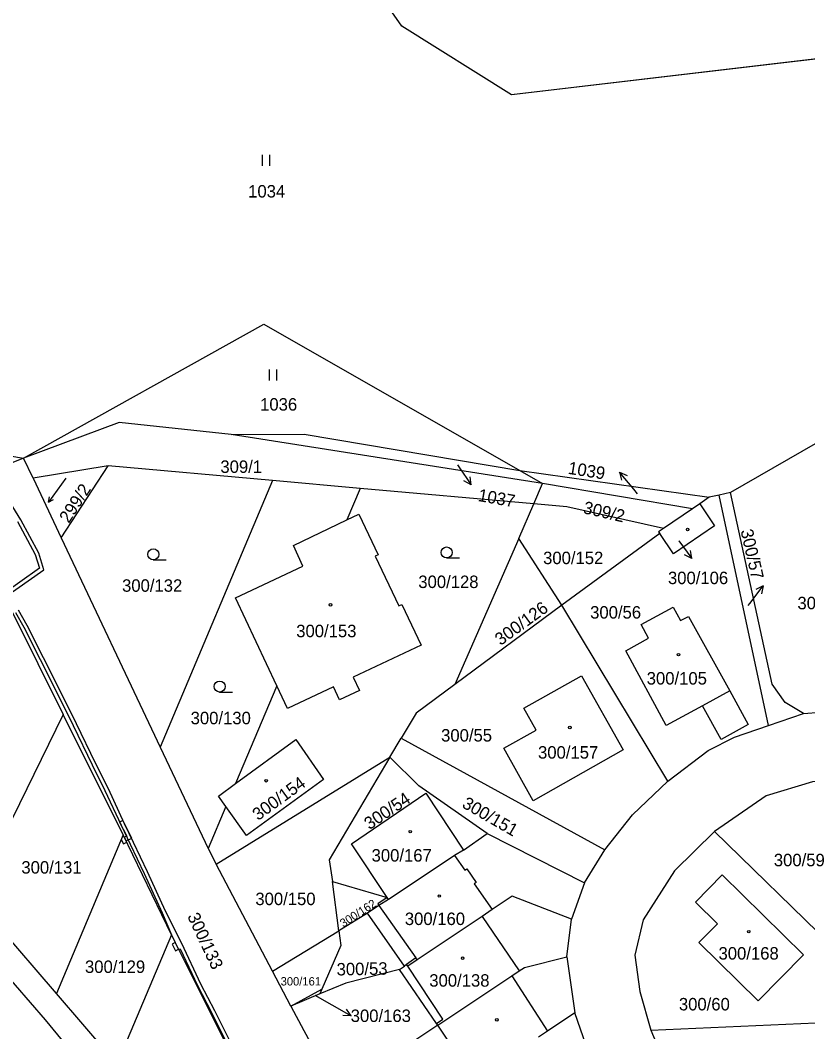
# Model space of a CAD drawing. Extents: x -757266 to -753360, y -1162585 to -1157740.
# Drawn here: x -754815.2 to -754707.7, y -1160582.8 to -1160444.8 of the extents above; entities that cross this region are included whole.
import ezdxf

# ---------------------------------------------------------------- set-up
doc = ezdxf.new("R2010")
doc.units = 0
for name, color, linetype in [('Hranice kat_území', 7, 'Continuous'), ('Hranice parcel', 7, 'Continuous'), ('Parcelní čísla', 7, 'Continuous'), ('Pop  PČ popisy', 7, 'Continuous'), ('Vnitřní kresba', 7, 'Continuous'), ('Věcná břemena k části', 7, 'Continuous'), ('Značky budov', 7, 'Continuous'), ('Značky kultur', 7, 'Continuous')]:
    doc.layers.add(name, color=color, linetype=linetype)

msp = doc.modelspace()

# ---------------------------------------------------------------- linework, layer by layer
at = {"layer": 'Hranice kat_území'}
msp.add_lwpolyline([(-754561.41, -1160428.29), (-754599.4, -1160427.7), (-754608.96, -1160459.95), (-754612, -1160470.2), (-754628.81, -1160464.16), (-754656.06, -1160454.38), (-754658.34, -1160453.56), (-754670.71, -1160445.87), (-754748.18, -1160454.98), (-754763.13, -1160445.62), (-754770.6, -1160434.89), (-754825.24, -1160422.53), (-754831.13, -1160423.76), (-754836.68, -1160424.92)], dxfattribs=at)
at = {"layer": 'Hranice parcel'}
for p, q in [((-754670.71, -1160445.87), (-754748.18, -1160454.98)), ((-754699.35, -1160498.35), (-754718.28, -1160509.25)), ((-754743.91, -1160508.02), (-754786.41, -1160501.34)), ((-754813.46, -1160507.31), (-754814.75, -1160504.58)), ((-754803.2, -1160505.6), (-754813.46, -1160507.31)), ((-754809.62, -1160515.44), (-754803.2, -1160505.6)), ((-754780.79, -1160507.61), (-754803.2, -1160505.6)), ((-754813.46, -1160507.31), (-754809.62, -1160515.44)), ((-754747.02, -1160506.24), (-754721.17, -1160509.88)), ((-754747.02, -1160506.24), (-754743.91, -1160508.02)), ((-754780.79, -1160507.61), (-754796.12, -1160544.01)), ((-754768.82, -1160508.68), (-754780.79, -1160507.61)), ((-754768.82, -1160508.68), (-754770.64, -1160512.99)), ((-754745.12, -1160510.8), (-754768.82, -1160508.68)), ((-754745.12, -1160510.8), (-754743.91, -1160508.02)), ((-754723.47, -1160511.47), (-754743.91, -1160508.02)), ((-754721.17, -1160509.88), (-754722.48, -1160510.8)), ((-754719.84, -1160509.59), (-754721.17, -1160509.88)), ((-754718.28, -1160509.25), (-754719.84, -1160509.59)), ((-754713.08, -1160541.04), (-754719.84, -1160509.59)), ((-754747.17, -1160515.5), (-754745.12, -1160510.8)), ((-754723.47, -1160511.47), (-754727.43, -1160514.15)), ((-754722.48, -1160510.8), (-754723.47, -1160511.47)), ((-754809.62, -1160515.44), (-754796.12, -1160544.01)), ((-754747.17, -1160515.5), (-754755.88, -1160535.43)), ((-754741.28, -1160524.64), (-754747.17, -1160515.5)), ((-754727.94, -1160514.85), (-754741.28, -1160524.64)), ((-754741.28, -1160524.64), (-754755.88, -1160535.43)), ((-754726.81, -1160548.63), (-754741.28, -1160524.64)), ((-754816.26, -1160525.62), (-754809.33, -1160539.55)), ((-754780.19, -1160535.61), (-754785.83, -1160548.97)), ((-754809.33, -1160539.55), (-754821.59, -1160564.48)), ((-754801.15, -1160555.98), (-754809.33, -1160539.55)), ((-754713.08, -1160541.04), (-754708.3, -1160539.4)), ((-754764.77, -1160545.37), (-754763.24, -1160542.79)), ((-754763.24, -1160542.79), (-754735.43, -1160558)), ((-754796.12, -1160544.01), (-754789.58, -1160557.84)), ((-754788.47, -1160559.96), (-754764.77, -1160545.37)), ((-754787.15, -1160552.09), (-754789.58, -1160557.84)), ((-754754.7, -1160558.03), (-754751.49, -1160555.79)), ((-754751.49, -1160555.79), (-754738.19, -1160562.51)), ((-754720.47, -1160555.5), (-754694.29, -1160581.04)), ((-754801.15, -1160555.98), (-754810.26, -1160577.6)), ((-754794.56, -1160569.62), (-754801.15, -1160555.98)), ((-754789.58, -1160557.84), (-754788.47, -1160559.96)), ((-754738.19, -1160562.51), (-754735.43, -1160558)), ((-754780.78, -1160574.56), (-754788.47, -1160559.96)), ((-754771.72, -1160569.05), (-754772.61, -1160562.35)), ((-754772.61, -1160562.35), (-754765.14, -1160564.5)), ((-754738.19, -1160562.51), (-754739.97, -1160567.47)), ((-754810.26, -1160577.6), (-754821.59, -1160564.48)), ((-754764.95, -1160564.79), (-754765.14, -1160564.5)), ((-754767.81, -1160566.67), (-754771.72, -1160569.05)), ((-754762.78, -1160573.86), (-754767.81, -1160566.67)), ((-754740.63, -1160572.62), (-754739.97, -1160567.47)), ((-754794.56, -1160569.62), (-754801.98, -1160587.2)), ((-754781.89, -1160594.97), (-754794.56, -1160569.62)), ((-754780.78, -1160574.56), (-754771.72, -1160569.05)), ((-754740.63, -1160572.62), (-754739.52, -1160580.26)), ((-754778.27, -1160579.33), (-754780.78, -1160574.56)), ((-754763.44, -1160574.32), (-754762.78, -1160573.86)), ((-754801.98, -1160587.2), (-754810.26, -1160577.6)), ((-754778.27, -1160579.33), (-754774.04, -1160577.01)), ((-754774.33, -1160577.68), (-754778.27, -1160579.33)), ((-754774.04, -1160577.01), (-754774.33, -1160577.68)), ((-754729.14, -1160582.6), (-754694.29, -1160581.04))]:
    msp.add_line(p, q, dxfattribs=at)
for points in [[(-754748.18, -1160454.98), (-754763.13, -1160445.62), (-754770.6, -1160434.89)], [(-754814.75, -1160504.58), (-754781.96, -1160486.26), (-754747.02, -1160506.24)], [(-754786.41, -1160501.34), (-754801.72, -1160499.7), (-754814.75, -1160504.58)], [(-754786.41, -1160501.34), (-754776.46, -1160501.29), (-754747.02, -1160506.24)], [(-754900.14, -1160504.92), (-754886.65, -1160509.79), (-754875.4, -1160511.64), (-754856.28, -1160511.06), (-754826.49, -1160502.54), (-754814.75, -1160504.58)], [(-754814.75, -1160504.58), (-754827.27, -1160509.62), (-754832.15, -1160509.43)], [(-754708.3, -1160539.4), (-754710.83, -1160537.88), (-754712.6, -1160535.4), (-754718.28, -1160509.25)], [(-754727.43, -1160514.15), (-754740.6, -1160511.2), (-754745.12, -1160510.8)], [(-754722.48, -1160510.8), (-754720.44, -1160513.8), (-754726.07, -1160517.61), (-754727.94, -1160514.85)], [(-754780.19, -1160535.61), (-754785.81, -1160523.61), (-754776.63, -1160519.29), (-754777.92, -1160516.46), (-754770.64, -1160512.99)], [(-754770.64, -1160512.99), (-754769, -1160512.21), (-754766.36, -1160517.76), (-754766.76, -1160517.95), (-754763.54, -1160524.72), (-754763.14, -1160524.53), (-754760.49, -1160530.08), (-754769.76, -1160534.46), (-754768.91, -1160536.27), (-754771.62, -1160537.55), (-754772.47, -1160535.75), (-754778.72, -1160538.71), (-754780.19, -1160535.61)], [(-754727.43, -1160514.15), (-754728.1, -1160514.61), (-754727.94, -1160514.85)], [(-754725.09, -1160526.73), (-754724, -1160526.15), (-754718.35, -1160536.32), (-754722.08, -1160538.36), (-754727.04, -1160541.04), (-754732.57, -1160530.83), (-754729.46, -1160529.12), (-754730.48, -1160527.27), (-754726.1, -1160524.9), (-754725.09, -1160526.73)], [(-754744.78, -1160541.67), (-754746.49, -1160538.67), (-754738.63, -1160534.24), (-754732.93, -1160544.34), (-754745.21, -1160551.32), (-754749.2, -1160544.12), (-754744.78, -1160541.67)], [(-754755.88, -1160535.43), (-754761.19, -1160539.36), (-754763.24, -1160542.79)], [(-754708.3, -1160539.4), (-754703.69, -1160539.02), (-754695.7, -1160539.88)], [(-754726.81, -1160548.63), (-754721.31, -1160544.46), (-754717.73, -1160542.64), (-754713.08, -1160541.04)], [(-754785.83, -1160548.97), (-754777.59, -1160542.96), (-754773.84, -1160548.39), (-754784.34, -1160556.04), (-754787.15, -1160552.09)], [(-754764.77, -1160545.37), (-754773.06, -1160559.36), (-754772.61, -1160562.35)], [(-754751.49, -1160555.79), (-754760.81, -1160549.27), (-754764.77, -1160545.37)], [(-754787.15, -1160552.09), (-754788.15, -1160550.69), (-754785.83, -1160548.97)], [(-754735.43, -1160558), (-754731.66, -1160553.22), (-754726.81, -1160548.63)], [(-754682.09, -1160554.71), (-754692.82, -1160549.97), (-754700.68, -1160548.61), (-754707.08, -1160548.74), (-754713.39, -1160550.62), (-754720.47, -1160555.5)], [(-754765.14, -1160564.5), (-754770.01, -1160557.17), (-754759.86, -1160550.29), (-754754.7, -1160558.03)], [(-754720.47, -1160555.5), (-754725.91, -1160560.87), (-754730.19, -1160567.56), (-754731.32, -1160572.38), (-754730.67, -1160577.36), (-754729.14, -1160582.6)], [(-754832.33, -1160557.56), (-754811.8, -1160581.2), (-754788.57, -1160609.52), (-754757.81, -1160649.38), (-754749.73, -1160667.84), (-754718.09, -1160730.78), (-754707.28, -1160759.93), (-754701.46, -1160778.37), (-754686.64, -1160826.48), (-754676.87, -1160861.18), (-754663.2, -1160911.68), (-754637.02, -1161012.69), (-754632.76, -1161025.61)], [(-754754.7, -1160558.03), (-754755.94, -1160558.77), (-754764.7, -1160564.63), (-754764.95, -1160564.79)], [(-754720.06, -1160568.1), (-754723.04, -1160565.14), (-754719.39, -1160561.44), (-754708.33, -1160572.35), (-754714.51, -1160578.61), (-754722.58, -1160570.66), (-754720.06, -1160568.1)], [(-754764.95, -1160564.79), (-754766.26, -1160565.6), (-754767.81, -1160566.67)], [(-754739.97, -1160567.47), (-754748.08, -1160564.34), (-754750.82, -1160566.17), (-754752.18, -1160567.09), (-754761.03, -1160573.02), (-754762.33, -1160573.9), (-754762.49, -1160573.66), (-754762.78, -1160573.86)], [(-754771.72, -1160569.05), (-754771.45, -1160571.08), (-754774.04, -1160577.01)], [(-754758.21, -1160581.94), (-754748.1, -1160575.19), (-754747.12, -1160574.53), (-754746.4, -1160574.05), (-754740.63, -1160572.62)], [(-754763.44, -1160574.32), (-754770.77, -1160576.18), (-754774.33, -1160577.68)], [(-754758.21, -1160581.94), (-754758.38, -1160581.7), (-754763.44, -1160574.32)], [(-754778.27, -1160579.33), (-754776.51, -1160582.67), (-754772.11, -1160590.8)], [(-754739.52, -1160580.26), (-754743.24, -1160582.74), (-754744.49, -1160583.58)], [(-754734.33, -1160594.03), (-754736.45, -1160589.03), (-754739.52, -1160580.26)], [(-754758.21, -1160581.94), (-754768.98, -1160589.13), (-754772.11, -1160590.8)], [(-754754.41, -1160590.2), (-754754.53, -1160590.01), (-754753.35, -1160589.23), (-754758.21, -1160581.94)], [(-754729.14, -1160582.6), (-754725.55, -1160591.14), (-754723.55, -1160595.26), (-754719.68, -1160601.5), (-754710.21, -1160615.49)]]:
    msp.add_lwpolyline(points, dxfattribs=at)
at = {"layer": 'Pop  PČ popisy'}
for p, q in [((-754755.54, -1160505.46), (-754755.35, -1160505.73)), ((-754755.35, -1160505.73), (-754753.672, -1160508.218)), ((-754753.672, -1160508.218), (-754753.817, -1160507.108)), ((-754731.49, -1160508.77), (-754733.419, -1160506.471)), ((-754733.419, -1160506.471), (-754732.392, -1160506.916)), ((-754733.419, -1160506.471), (-754733.159, -1160507.56)), ((-754753.672, -1160508.218), (-754754.647, -1160507.668)), ((-754730.95, -1160509.42), (-754731.49, -1160508.77)), ((-754725.32, -1160515.82), (-754725.31, -1160515.84)), ((-754725.31, -1160515.84), (-754723.546, -1160518.268)), ((-754723.546, -1160518.268), (-754723.73, -1160517.163)), ((-754723.546, -1160518.268), (-754724.54, -1160517.752)), ((-754715.64, -1160524.38), (-754713.834, -1160521.983)), ((-754713.834, -1160521.983), (-754714.837, -1160522.482)), ((-754713.834, -1160521.983), (-754714.037, -1160523.084)), ((-754715.86, -1160524.68), (-754715.64, -1160524.38)), ((-754775.01, -1160577.82), (-754772.66, -1160579.17)), ((-754772.66, -1160579.17), (-754770.061, -1160580.67)), ((-754770.061, -1160580.67), (-754771.179, -1160580.603)), ((-754770.061, -1160580.67), (-754770.678, -1160579.736))]:
    msp.add_line(p, q, dxfattribs=at)
at = {"layer": 'Vnitřní kresba'}
for p, q in [((-754718.35, -1160536.32), (-754715.87, -1160540.92)), ((-754719.54, -1160542.94), (-754722.08, -1160538.36)), ((-754715.87, -1160540.92), (-754719.54, -1160542.94)), ((-754755.94, -1160558.77), (-754754.53, -1160560.8)), ((-754754.53, -1160560.8), (-754754.26, -1160560.61)), ((-754754.26, -1160560.61), (-754752.98, -1160562.46)), ((-754752.98, -1160562.46), (-754753.25, -1160562.65)), ((-754753.25, -1160562.65), (-754750.82, -1160566.17)), ((-754765.14, -1160564.5), (-754766.41, -1160565.38)), ((-754766.41, -1160565.38), (-754766.26, -1160565.6)), ((-754766.26, -1160565.6), (-754761.21, -1160572.75)), ((-754752.18, -1160567.09), (-754747.12, -1160574.53)), ((-754761.21, -1160572.75), (-754762.49, -1160573.66)), ((-754761.03, -1160573.02), (-754761.21, -1160572.75)), ((-754757.53, -1160581.12), (-754762.33, -1160573.9)), ((-754748.1, -1160575.19), (-754743.24, -1160582.74)), ((-754758.38, -1160581.7), (-754757.53, -1160581.12))]:
    msp.add_line(p, q, dxfattribs=at)
at = {"layer": 'Věcná břemena k části'}
for points in [[(-754817.48, -1160523.68), (-754812, -1160519.79), (-754812.69, -1160517.51), (-754815.13, -1160512.96), (-754816.56, -1160510.59)], [(-754815.57, -1160513.2), (-754813.15, -1160517.71), (-754812.58, -1160519.59), (-754817.96, -1160523.41)], [(-754785.53, -1160586.25), (-754788.65, -1160580), (-754790.56, -1160576.32), (-754793.17, -1160570.81), (-754795.39, -1160566.38), (-754797.83, -1160561.02), (-754799.74, -1160557.01), (-754800.97, -1160554.44), (-754803.18, -1160549.67), (-754804.94, -1160546.17), (-754807.52, -1160540.81), (-754809.89, -1160536.05), (-754812.05, -1160531.82), (-754814.27, -1160527.38), (-754815.45, -1160525.31)], [(-754815.85, -1160525.61), (-754814.71, -1160527.62), (-754812.49, -1160532.04), (-754810.33, -1160536.27), (-754807.96, -1160541.03), (-754805.38, -1160546.39), (-754803.64, -1160549.89), (-754801.43, -1160554.66), (-754800.2, -1160557.23), (-754798.29, -1160561.24), (-754795.85, -1160566.6), (-754794.56, -1160569.62), (-754794.04, -1160570.67), (-754793.59, -1160571.56), (-754793.39, -1160571.53), (-754791, -1160576.54), (-754789.09, -1160580.22), (-754785.97, -1160586.47)]]:
    msp.add_lwpolyline(points, dxfattribs=at)
for points in [[(-754801, -1160556.3), (-754800.77, -1160556.76), (-754799.96, -1160556.42), (-754801.2, -1160554.01), (-754801.65, -1160554.24), (-754800.66, -1160556.16)], [(-754801.41, -1160556.6), (-754801.12, -1160557.2), (-754800.67, -1160556.98), (-754800.77, -1160556.76), (-754801, -1160556.3), (-754801.1, -1160556.08), (-754801.21, -1160556.13)], [(-754794.04, -1160570.67), (-754794.48, -1160570.89), (-754794.03, -1160571.79), (-754793.59, -1160571.56)]]:
    msp.add_lwpolyline(points, close=True, dxfattribs=at)
at = {"layer": 'Značky budov'}
for centre in [(-754724.1268, -1160514.2892), (-754772.8668, -1160524.5792), (-754725.3668, -1160531.3792), (-754740.1968, -1160541.3092), (-754781.6468, -1160548.5792), (-754761.9768, -1160555.5292), (-754758.0168, -1160564.3092), (-754715.7868, -1160569.1792), (-754754.8268, -1160572.7892), (-754750.1668, -1160581.1992)]:
    msp.add_circle(centre, 0.175, dxfattribs=at)
at = {"layer": 'Značky kultur'}
for p, q in [((-754782.161, -1160464.67), (-754782.161, -1160463.17)), ((-754781.16, -1160464.67), (-754781.16, -1160463.17)), ((-754781.181, -1160493.96), (-754781.181, -1160492.46)), ((-754780.18, -1160493.96), (-754780.18, -1160492.46)), ((-754808.97, -1160507.3), (-754811.333, -1160510.552)), ((-754811.333, -1160510.552), (-754811.22, -1160509.825)), ((-754811.333, -1160510.552), (-754810.676, -1160510.22)), ((-754797.043, -1160518.44), (-754795.293, -1160518.44)), ((-754757.013, -1160518.18), (-754755.263, -1160518.18)), ((-754787.993, -1160536.47), (-754786.243, -1160536.47))]:
    msp.add_line(p, q, dxfattribs=at)
for centre in [(-754797.0429, -1160517.6898), (-754757.0129, -1160517.4298), (-754787.9929, -1160535.7198)]:
    msp.add_circle(centre, 0.75, dxfattribs=at)

# ---------------------------------------------------------------- texts
at = {"layer": 'Parcelní čísla'}
for s, height, p in [('1034', 1.7, (-754784.1, -1160468.99)), ('1036', 1.7, (-754782.47, -1160498.07)), ('309/1', 1.7, (-754787.89, -1160506.57)), ('300/152', 1.7, (-754743.85, -1160519.02)), ('300/106', 1.7, (-754726.81, -1160521.748)), ('300/132', 1.7, (-754801.31, -1160522.79)), ('300/128', 1.7, (-754760.88, -1160522.28)), ('300/58', 1.7, (-754709.14, -1160525.18)), ('300/56', 1.7, (-754737.43, -1160526.45)), ('300/153', 1.7, (-754777.54, -1160528.99)), ('300/105', 1.7, (-754729.71, -1160535.45)), ('300/130', 1.7, (-754791.95, -1160540.87)), ('300/55', 1.7, (-754757.77, -1160543.23)), ('300/157', 1.7, (-754744.54, -1160545.56)), ('300/167', 1.7, (-754767.256, -1160559.61)), ('300/59', 1.7, (-754712.36, -1160560.25)), ('300/131', 1.7, (-754815.05, -1160561.25)), ('300/150', 1.7, (-754783.12, -1160565.55)), ('300/160', 1.7, (-754762.72, -1160568.27)), ('300/168', 1.7, (-754719.91, -1160572.98)), ('300/129', 1.7, (-754806.37, -1160574.81)), ('300/138', 1.7, (-754759.38, -1160576.68)), ('300/161', 1.139, (-754779.669, -1160576.519)), ('300/60', 1.7, (-754725.32, -1160579.92)), ('300/163', 1.7, (-754770.106, -1160581.5))]:
    msp.add_text(s, height=height, dxfattribs=at).set_placement(p)
for s, height, rotation, p in [('1039', 1.7, 351, (-754740.528, -1160506.688)), ('299/2', 1.7, 57, (-754808.577, -1160513.542)), ('1037', 1.7, 349.999997, (-754752.814, -1160510.395)), ('309/2', 1.7, 347, (-754738.471, -1160512.058)), ('300/57', 1.7, 283, (-754716.918, -1160514.451)), ('300/126', 1.7, 36, (-754749.65, -1160530.197)), ('300/154', 1.7, 36, (-754782.74, -1160554.087)), ('300/54', 1.7, 34, (-754767.544, -1160555.334)), ('300/151', 1.7, 329.999997, (-754755.035, -1160552.136)), ('300/162', 1.139, 33, (-754771.112, -1160568.635)), ('300/133', 1.7, 295, (-754792.44, -1160567.059)), ('300/53', 1.7, 1, (-754772.015, -1160575.159))]:
    msp.add_text(s, height=height, rotation=rotation, dxfattribs=at).set_placement(p)

doc.saveas('drawing.dxf')
